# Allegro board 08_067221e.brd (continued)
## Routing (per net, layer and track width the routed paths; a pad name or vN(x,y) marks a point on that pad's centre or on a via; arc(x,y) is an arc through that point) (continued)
GND_ISO: length 25.4
  TOP w0.508: 170.42,21.67 P22.1 170.42,19.56 ; R65.1 162.36,35.94 ; R65.1 161.79,35.32 ; R65.1 161.79,36.56 ; P22.8 173.25,28.93
  L2_GND w0.508: P22.8 173.25,28.93 ; 170.67,21.41 P22.1 170.67,19.82
  L3_SIG w0.508: P22.8 173.25,28.93 ; 170.67,19.82 P22.1 170.67,21.41
  L5_GND w0.508: 170.67,19.82 P22.1 170.67,21.41 ; P22.8 173.25,28.93
  BOTTOM w0.508: 173.25,28.85 P22.8 P22.6 ; 165,32.52 R247.2 ; R247.2 165,34.79 ; R247.2 164.22,33.66 ; 170.42,19.56 P22.1 170.42,21.67
  vias: v1(150.62,33.53) v1(151.76,33.53) v1(152.78,33.53) v1(153.8,33.53) v1(154.81,33.53) v1(155.83,33.53) v1(156.84,33.53) v1(157.61,33.53) v1(157.66,31.09) v1(157.66,29.82) v1(160.28,31.35) v1(160.28,30.08) v1(161.8,34.16) v1(162.69,35.94) v1(162.81,33.15) v1(163.83,34.42) v1(163.83,33.66) v1(163.83,32.89) v1(163.83,32.13) v1(164.97,30.99) v1(165.35,26.16) v1(165.99,29.97) v1(166.81,12) v1(166.81,11.37) v1(166.81,10.73) v1(166.88,29.08) v1(167.45,12) v1(167.45,11.37) v1(167.45,10.73) v1(167.8,23.71) v1(168.1,27.12) v1(168.08,12) v1(168.08,11.37) v1(168.08,10.73) v1(168.96,23.18) v1(169,26.22) v1(170.1,22.62) v1(170.2,25.8)
GND_SHIELD_A: length 112.3
  TOP w0.508: P22.14 176.15,28.45 175.26,28.45 175.26,19.94 176.15,19.94 P22.13
  TOP w0.635: TP4.1 175.26,12.98 C99.2 176.15,13.87 P22.13
  L2_GND w0.508: P22.14 176.15,28.45 175.26,28.45 175.26,19.94 176.15,19.94 P22.13
  L3_SIG w0.508: P22.14 176.15,28.45 175.26,28.45 175.26,19.94 176.15,19.94 P22.13
  L4_PWR w0.508: P22.13 176.15,19.94 175.26,19.94 175.26,28.45 176.15,28.45 P22.14
  L5_GND w0.508: P22.14 176.15,28.45 175.26,28.45 175.26,19.94 176.15,19.94 P22.13
  BOTTOM w0.508: P22.14 176.15,28.45 175.26,28.45 175.26,19.94 176.15,19.94 P22.13
VDD_3V3: length 147.9
  TOP w0.254: U6.56 24.56,44.78 24.01,45.33 24.01,46.48 v1(24,46.48) C27.2 ; U7.45 C107.2 ; U6.38 33.71,46.62 34.04,46.95 34.25,46.95 34.67,47.37 C26.2 ; U6.18 34.21,35.81 34.46,35.56 v1(34.92,35.56) ; v1(108.2,40.64) 108.2,40.12 108.37,39.96 108.37,39.49 108.19,39.32 U9.46 ; U6.2 26.21,35.18 25.77,34.75 C56.2 ; C109.2 52.19,32.69 52.57,33.08 U7.51 ; U7.5 C110.2 ; C60.1 58.55,31.97 58.08,32.45 U7.62 ; U7.32 C66.2
  TOP w0.406: R53.2 v1(129.28,14.22) ; v1(128.37,17.39) C171.1 129.17,17.4 U27.5 ; R126.2 v1(137.29,19.94) ; v1(133.22,17.39) C170.1 133.99,17.4 U26.5 ; R39.2 v1(134.11,14.22) ; R122.2 v1(132.59,19.94)
  TOP w0.508: C66.2 51.63,47.17 v1(51.63,47.94) ; v1(47.18,37.4) 47.92,37.4 C107.2 ; C56.2 v1(25.77,34.04) ; v1(52.2,31.56) 52.2,32.25 C109.2 ; v1(146.18,18.65) C169.1 146.19,17.91 U25.5 ; R243.2 v1(129.04,10.67) ; v1(82.68,14.86) C176.2 ; U28.5 139.21,17.91 C172.2 v1(139.19,18.67) ; v1(54.23,53.85) 54.23,54.56 R33.2 ; U24.5 120.58,64.58 v1(121.67,64.58) ; v1(108.2,41.15) v1(108.2,40.64) ; DS1.A 129.23,62.74 v1(130.43,62.74) ; R187.1 63.83,44.26 v1(63.82,44.26) ; v1(34.92,35.56) 35.43,35.06 C129.2 ; E12.2 125.49,15.56 ; E12.2 124.74,16.43 ; E12.2 124.74,14.68 ; v1(115.95,10.67) R148.2 ; R12.2 v1(113.03,22.99) R22.2 ; C26.2 v1(35.19,46.74) ; R107.1 v1(38.48,38.23) ; R118.1 v1(114.93,25.4) ; R180.2 v1(156.6,18.16) ; R74.2 v1(142.88,4.06) ; v1(136.9,11.95) C4.1 E16.2 ; U15.8 125.22,12.18 C94.1 v1(125.96,12.19) ; R15.2 v1(130.55,10.67) ; v1(116.9,63.88) C1.2 U1.5 ; v1(114.87,66.04) R2.1 ; v1(115.95,9.4) R139.2 ; R26.2 v1(130.55,8.13) ; v1(60.2,29.59) 60.19,29.6 v1(60.19,30.33) 59.51,31.01 C108.2 C60.1 ; R238.2 v1(147.7,19.43) ; v1(115.95,8.13) R137.2 ; v1(98.42,15.24) C179.2 ; R19.2 v1(130.55,9.4) ; v1(62.67,38.73) 62.67,37.95 C110.2 ; v1(115.51,67.63) R101.1 ; E9.2 v1(12.7,45.94) ; R95.2 v1(145.92,14.1) ; v1(85.85,14.1) R119.1 ; v1(51.05,50.03) R142.2 ; v1(111.57,66.36) R5.1 ; v1(118.63,57.44) C163.2 C5.2 U2.4 117.71,61.69 R9.1 ; v1(37.44,27.31) C67.1 39.75,27.31 Y1.4 39.89,27.31 R115.2
  L4_PWR w0.508: 81.12,10.63 P4.3 ; P4.3 82.71,10.63 ; P4.3 81.12,12.23 ; P4.3 82.71,12.23 ; 98.39,10.63 P6.2 ; P6.2 99.98,12.23 ; P6.2 98.39,12.23 ; P6.2 99.98,10.63 ; 64.71,46.23 TP24.1 ; TP24.1 64.71,48 ; TP24.1 66.48,46.23 ; TP24.1 66.48,48 ; P8.7 47.24,50.92 ; P8.7 45.47,49.15 ; P8.7 47.24,49.15 ; P8.7 45.47,50.92 ; 7.17,56 JP47.1 7.17,54.23
  BOTTOM w0.305: v1(14.1,36.2) 14.1,36.65 13.79,36.96 11.94,36.96 11.74,36.76 C175.2 11.74,35.74 11.3,35.3 U4.5
  BOTTOM w0.381: v1(70.48,15.68) 69.66,15.68 D8.5 D8.2 ; v1(70.46,18.54) 69.66,18.54 D9.2 D9.5
  BOTTOM w0.508: v1(58.8,16.38) 60.47,16.38 U20.4 ; v1(161.66,4.08) R231.1 ; v1(111.5,57.72) R166.2 v1(112.27,56.9) ; v1(50.48,27.24) C154.2 U5.8 ; R185.2 50.21,42.48 v1(51.37,42.48) ; v1(108.2,40.64) v1(108.2,41.15) C124.2 C97.2 ; U17.8 C145.2 34.48,17.32 v1(34.48,18.1) 34.47,18.11 C82.2 ; Q3.3 22.86,48.02 R175.2 ; v1(100.15,33.02) 100.94,33.8 E1.1 ; U18.8 C146.2 22.1,17.32 v1(22.1,18.1) ; R174.2 2.98,51.82 JP47.1 ; v1(87.69,61.85) R161.2
  BOTTOM w1.016: v1(63.82,44.26) 65.6,46.03 TP24.1
  vias: v1(19.94,58.29) v1(19.94,56.77) v1(20.57,57.53) v1(21.72,49.28) v1(21.72,48.77) v1(36.7,30.1) v1(36.7,29.46) v1(54.23,53.02) v1(54.23,52.2) v1(54.99,53.85) v1(54.99,53.02) v1(54.99,52.2) v1(60.12,51.26) v1(60.13,50.48) v1(60.88,51.26) v1(60.88,50.5) v1(61.64,51.26) v1(61.64,50.5) v1(62.23,29.97) v1(62.23,29.34) v1(62.23,28.7) v1(62.87,29.97) v1(62.87,29.34) v1(62.87,28.7) v1(70.36,13.46) v1(70.36,12.57) v1(125.86,16.26) v1(125.86,15.62) v1(125.86,14.99) v1(128.27,39.12) v1(128.27,38.61) v1(128.78,39.12) v1(128.78,38.61)
VDD_5V: length 22.5
  TOP w0.508: L1.2 v1(158.75,47.79)
  L3_SIG w0.508: 92.2,51.81 TP3.1 ; TP3.1 93.98,51.81 ; TP3.1 93.98,50.04 ; TP3.1 92.2,50.04
  BOTTOM w0.508: v1(158.75,47.79) D10.C 159.51,45.71 160.02,45.2 160.02,40.89 161.26,39.65 P10.9
  vias: v1(89.47,52.07) v1(89.47,51.31) v1(90.3,52.07) v1(90.3,51.31)
VDD_5V_BPORT: length 3.1
  TOP w0.508: R36.2 86.85,53.8 v1(85.47,53.8)
  BOTTOM w0.508: v1(112.27,54.61) R165.2 v1(111.5,55.44)
  vias: v1(85.47,53.09)
1452_RESET: length 122.4
  TOP w0.178: U6.24 35.65,39.28 R107.2 36.96,37.98 36.96,37.62 v1(37.21,37.36)
  TOP w0.203: v1(126.05,64.9) R6.1
  L3_SIG w0.203: v1(126.05,64.9) 124.4,63.25 114.55,63.25 112.1,65.7 102.08,65.7 98.74,62.36 90.3,62.36 89.79,62.86 89.79,64.14 89.28,64.64 88.01,64.64 87.5,64.14 85.85,64.14 85.5,64.48 82.2,64.48 78.44,60.72 78.44,48.53 72.81,42.9 66,42.9 65.98,42.93 65.97,42.93 64,44.89 59.5,44.89 v1(58.55,43.94)
  BOTTOM w0.178: v1(58.55,43.94) 58.55,42.93 57.28,41.66 49.78,41.66 48.51,40.39 41.91,40.39 41.02,41.27 39.62,41.27 39.12,40.77 39.12,37.72 38.76,37.36 v1(37.21,37.36) 36.89,37.36 36.71,37.54 R107.2
AD243X_ADR1_SS: length 142.6
  TOP w0.178: R195.1 v1(112.27,25.4) ; P15.23 17.2,42.67 15.11,42.67 14.68,42.24 14.68,35.74 14,35.05 R100.1
  L3_SIG w0.178: v1(112.27,25.4) 111.37,24.49 105.04,24.49 104.26,25.27 96.01,25.27 93.73,27.56 67.18,27.56 66.42,26.8 57.95,26.8 56.11,28.63 56.11,32.66 55.3,33.48 51.64,33.48 51.04,32.88 49.17,32.88 47.53,31.24 20.7,31.24 19.48,32.46 19.48,34.37 18.92,34.92 17.58,34.92 17.14,35.36 17.14,36.7 17.54,37.1 17.54,37.83 17.22,38.15 17.22,42.7 P15.23
  BOTTOM w0.203: P32.79 12,44.13 14.48,46.61 14.48,47.12 14.86,47.5 16.76,47.5 17.14,47.12 17.14,45.01 P15.23
AD243X_AN: length 22.9
  TOP w0.241: U9.28 114.09,33.93 arc(114.14,33.96) 114.2,33.97 115.57,33.97 arc(115.69,33.95) 115.78,33.88 120.11,29.56 122.51,27.15 arc(123.23,26.67) 124.08,26.5 129.04,26.5 C30.2 129.46,26.21 129.76,26.5 130.34,26.5 130.76,26.08 L2.2 130.98,26.08 131.41,26.51 132.31,26.51 L4.1
AD243X_AP: length 22.9
  TOP w0.241: L5.1 132.31,26.92 131.45,26.92 131.04,27.33 L3.1 130.71,27.33 130.29,26.91 129.81,26.91 129.51,27.21 C30.1 129.04,26.91 124.08,26.91 arc(123.39,27.05) 122.8,27.44 120.4,29.84 116.07,34.17 arc(115.84,34.32) 115.57,34.38 114.2,34.38 arc(114.14,34.39) 114.09,34.42 U9.29
AD243X_BCLK: length 185.1
  TOP w0.178: C10.2 v1(35.69,51) R45.2 ; R62.2 v1(21.46,45.34) ; R241.1 v1(99.06,32.38) 98.55,32.38 98.17,32 98.17,30.39 98.72,29.84 102.14,29.84 103.33,28.65 103.33,23.54 106.81,20.07 JP1.4
  L3_SIG w0.203: v1(56.4,51.05) 56.02,50.67 54.42,50.67 53.15,51.94 53.15,53.59 51.66,55.08 50.29,55.08 48.01,57.37 44.59,57.37 44.33,57.62 39.71,57.62 37.59,55.5 37.59,50.93 37.13,50.46 36.22,50.46 v1(35.69,51)
  BOTTOM w0.178: v1(99.06,32.38) 98.54,32.91 98.54,34.44 99.06,34.96 99.06,35.81 99.07,35.82 99.07,36.57 94.2,41.44 64.29,41.44 58.93,46.8 58.93,50.35 57.7,51.57 56.93,51.57 v1(56.4,51.05) R172.2 ; C151.1 10.55,17.52 10.92,17.14 17.07,17.14 P15.1 19.47,17.01 19.47,18.71 21.34,20.57 21.34,29 22.86,30.52 22.86,34.42 23.37,34.92 23.37,41.22 21.48,43.11 21.48,44.41 21.46,44.42 v1(21.46,45.34) 21.07,45.73 21.07,54.34 21.72,54.99 29.69,54.99 31.51,53.17 31.51,51.3 32.74,50.06 35.22,50.06 35.69,50.53 v1(35.69,51)
  BOTTOM w0.203: C151.1 10.42,18.8 10.42,18.83 9.91,19.34 9.91,19.8 9.71,20 P32.3
AD243X_BCM: length 8.9
  TOP w0.254: v1(112.46,37.02) 112.86,37.42 U9.35
  BOTTOM w0.381: v1(112.46,37.02) 112.46,37.34 112.08,37.72 111.93,37.72 C13.2 111.42,38.23 111.42,41.57 112.65,42.8 C14.2
AD243X_BN: length 23
  TOP w0.241: L11.1 132.32,44.33 131.62,44.33 131.19,44.77 L9.1 130.66,44.77 130.23,44.34 129.72,44.34 129.42,44.63 C45.1 129.04,44.34 124.08,44.34 arc(123.27,44.17) 122.58,43.72 120.97,42.1 115.87,37 arc(115.73,36.91) 115.57,36.88 114.4,36.88 114.36,36.92 U9.34
AD243X_BP: length 22.9
  TOP w0.241: U9.33 114.36,36.42 114.4,36.47 115.57,36.47 arc(115.89,36.53) 116.16,36.71 121.26,41.81 122.87,43.43 arc(123.43,43.8) 124.08,43.93 129.04,43.93 C45.2 129.4,43.63 129.7,43.93 130.25,43.93 130.68,43.5 L8.2 131.17,43.5 131.6,43.93 132.32,43.93 L10.1
AD243X_DRX0: length 145.7
  TOP w0.178: R47.2 v1(34.54,51) C11.2
  TOP w0.203: JP6.1 88.42,38.86 68.83,38.86 66.92,40.77 v1(66.92,43.94) ; R57.2 53,51.13 v1(50.46,51.13)
  L3_SIG w0.203: v1(66.92,43.94) 66.29,43.94 63.78,46.46 63.78,47.79 61.96,49.61 59.77,49.61 59.23,50.15 51.71,50.15 51.29,50.56 51.03,50.56 v1(50.46,51.13) 50.8,51.47 50.8,52.91 50.55,53.16 50.55,53.98 47.56,56.96 43.62,56.96 43.37,57.21 40.07,57.21 38.86,56.01 38.86,51.62 37.3,50.06 35.48,50.06 v1(34.54,51)
  BOTTOM w0.178: v1(34.54,51) 33.98,51.56 33.4,51.56 32.99,51.97 32.99,54.73 31.85,55.88 21.34,55.88 20.31,54.85 20.31,43.2 22.61,40.9 22.61,35.43 21.08,33.91 21.08,29.9 20.32,29.13 20.32,25.47 P15.7 17.21,22.36 15.33,22.36 15.15,22.54 P32.11
AD243X_DRX1: length 147.5
  TOP w0.178: R48.2 C12.2 32.65,51.7 32.77,51.82 32.77,52.58 v1(33.53,53.34)
  TOP w0.203: JP9.1 88.37,42.29 71.95,42.29 v1(70.29,43.94)
  L3_SIG w0.203: v1(70.29,43.94) 69.66,43.31 66.17,43.31 63.37,46.1 63.37,47.62 61.86,49.14 59.42,49.14 59.28,49.28 58.8,49.28 58.34,49.74 51.52,49.74 51.27,49.5 50.83,49.5 49.82,50.51 49.82,51.33 50.34,51.86 50.34,52.79 48.66,54.47 48.02,54.47 45.97,56.52 43.43,56.52 43.14,56.81 40.3,56.81 39.36,55.87 39.36,51.54 37.47,49.65 33.41,49.65 32.51,50.55 32.51,52.32 v1(33.53,53.34)
  BOTTOM w0.178: v1(33.53,53.34) 33.53,54.74 32,56.26 21.18,56.26 21.17,56.25 21.07,56.25 19.93,55.11 19.93,43.04 22.2,40.77 22.2,35.66 20.7,34.16 20.7,30.09 19.81,29.2 19.81,27.51 P15.9 17.13,24.83 14.67,24.83 13.65,23.81 P32.15
AD243X_GPIO7: length 145.9
  TOP w0.178: JP1.2 113.59,21.29 107.11,21.29 106.3,22.1 R14.1
  L3_SIG w0.203: v1(12.37,29.97) 12.37,26.23 13.72,24.89 18.8,24.89 19.67,24.02 19.67,22.19 20.07,21.79 20.07,20.19 20.96,19.3 30.1,19.3 30.73,19.94 34.75,19.94 36.3,18.39 47.02,18.39 48.01,17.4 67.44,17.4 67.56,17.27 69.66,17.27 70.16,17.78 70.8,17.78 72.06,19.04 96.33,19.04 98.61,16.75 105.55,16.75 110.07,12.23 115.14,12.23 116.94,14.03 116.94,15.78 114.81,17.91 JP1.2
  BOTTOM w0.178: R189.1 11.97,30.86 11.34,31.5 11.34,32.93 11.55,33.14 11.83,33.14 12.06,33.38 12.06,34.16 12.19,34.29 U4.2
  BOTTOM w0.203: v1(12.37,29.97) 12.37,30.78 R189.1
AD243X_IOVDD: length 14.9
  TOP w0.178: v1(110.87,30.73) 111.19,31.06 U9.21
  TOP w0.203: v1(107.42,32.68) 107.18,32.93 U9.11
  L4_PWR w0.508: 67.82,24.77 TP10.1 ; TP10.1 69.59,26.54 ; TP10.1 69.59,24.77 ; TP10.1 67.82,26.54
  BOTTOM w0.508: R7.2 110.87,29.97 v1(110.87,30.73) 110.87,31.49 C22.2 ; E1.2 105.16,34.8 106.55,33.41 C40.2 107.42,33.36 v1(107.42,32.68)
AD243X_IRQ: length 167.1
  TOP w0.178: R69.1 30.61,50.93 30.35,51.18 30.35,52.32 v1(30.99,52.96) ; R38.2 101.97,27.91 101.57,28.32 v1(100.33,28.32) ; U9.24 112.69,29.55 113.92,28.32 114.65,28.32 114.93,28.03 R118.2 115.45,27.42 115.82,27.05 v1(115.82,25.4) ; P15.29 19.68,50.09 19.68,43.27 18.96,42.54 17.78,42.54 17.02,41.78 v1(17.02,37.46)
  L3_SIG w0.178: P15.29 18.29,51.43 17.22,52.5 17.22,54.82 17.51,55.11 29.6,55.11 30.99,53.72 v1(30.99,52.96) 30.35,52.32 30.35,51.05 32.53,48.88 37.86,48.88 39.15,50.16 v1(39.5,50.16)
  BOTTOM w0.178: v1(39.5,50.16) 40.64,51.31 47.62,51.31 48.13,50.8 48.13,48.51 54.23,42.42 56.9,42.42 57.66,43.18 57.66,44.32 58.17,44.83 58.93,44.83 63.75,40 66.99,40 68.55,38.45 95.57,38.45 97.27,36.76 97.27,31.3 98.6,29.97 98.68,29.97 v1(100.33,28.32) 103.63,25.02 104.51,25.02 105.15,24.38 111.99,24.38 113.53,25.92 115.3,25.92 v1(115.82,25.4) ; v1(17.02,37.46) 14.99,37.46 13.89,38.56 10.87,38.56 10.1,37.78 P32.59
AD243X_ISENSEP: length 29.6
  TOP w0.203: U9.42 110.19,39.15 110.29,39.25 110.29,39.56 110.81,40.08 110.81,42.81 112.79,44.79 112.79,47.41 111.54,48.65 102.73,48.65 v1(97.28,54.1)
  BOTTOM w0.305: R182.1 96.77,53.59 v1(97.28,54.1)
AD243X_MISO: length 180.1
  TOP w0.178: R86.1 v1(2.42,39.05)
  L3_SIG w0.178: v1(152.65,9.14) 151.94,8.43 136.09,8.43 133.05,5.38 114.71,5.38 106.13,13.96 86.45,13.96 85.95,13.46 71.98,13.46 70.57,12.05 70.14,12.05 68.48,13.72 58.36,13.72 57.22,14.86 47.34,14.86 45.52,16.68 22.05,16.68 19,13.63 13.39,13.63 12.36,14.66 12.36,17.58 5.33,24.61 5.33,36.14 v1(2.42,39.05)
  BOTTOM w0.203: R232.1 v1(152.65,9.14)
AD243X_MISO_SW: length 128.4
  TOP w0.178: v1(6.86,35.19) 6.86,35.55 6.68,35.72 2.62,35.72 2.42,35.93 R92.1 ; R120.1 v1(108.84,25.4)
  L3_SIG w0.178: P15.19 19.46,37.62 19.46,35.66 20.24,34.87 20.24,33.1 21.34,32 47.21,32 48.85,33.64 50.73,33.64 51.32,34.24 55.86,34.24 56.88,33.22 56.88,28.94 58.26,27.56 66.11,27.56 66.87,28.32 94.23,28.32 96.39,26.17 108.06,26.17 v1(108.84,25.4) ; v1(6.86,35.19) 7.89,35.19 8.13,35.43 8.13,38.86 7.94,39.05 v1(6.86,39.05)
  BOTTOM w0.178: P15.19 17.07,40 12.95,40 12,39.05 P32.63 v1(6.86,39.05)
AD243X_MOSI: length 179.6
  TOP w0.178: R97.1 v1(2.42,34.1)
  L3_SIG w0.178: v1(156.45,9.13) 155.32,8 136.21,8 133.2,5 114.55,5 105.98,13.58 87.15,13.58 86.38,12.81 71.87,12.81 70.73,11.67 69.98,11.67 68.32,13.33 58.2,13.33 57.06,14.48 47.12,14.48 45.34,16.26 22.23,16.26 19.18,13.21 13.21,13.21 11.94,14.48 11.94,17.4 4.95,24.38 4.95,31.57 v1(2.42,34.1)
  BOTTOM w0.203: R223.1 v1(156.45,9.13)
AD243X_MOSI_SW: length 139.1
  TOP w0.178: v1(6.86,30.21) 2.93,30.21 2.42,30.73 R111.1 ; R11.1 v1(109.98,25.4)
  L3_SIG w0.178: P15.21 18.34,40.4 19.84,38.9 19.84,35.88 20.7,35.02 20.7,33.27 21.59,32.38 47.06,32.38 48.69,34.02 50.57,34.02 51.16,34.62 56.02,34.62 57.26,33.38 57.26,29.1 58.42,27.94 65.95,27.94 66.71,28.7 94.49,28.7 96.64,26.55 108.83,26.55 v1(109.98,25.4) ; v1(6.86,40.32) 8.19,40.32 8.51,40 8.51,30.48 8.24,30.21 v1(6.86,30.21)
  BOTTOM w0.178: P15.21 17.07,42.54 14.1,42.54 11.87,40.32 P32.67 v1(6.86,40.32)
AD243X_RESET: length 106.1
  TOP w0.203: v1(112.39,32.64) 112.72,32.64 112.93,32.42 U9.25 ; R3.1 125.34,65.91 v1(126.05,65.91) 127.57,65.91 P23.1
  L3_SIG w0.203: v1(126.05,65.91) 126.64,65.32 126.64,63.6 125.28,62.23 113.79,62.23 112.01,64.01 102.36,64.01 99.31,60.96 93.57,60.96 90.3,57.68 85.37,57.68 80.01,52.32 80.01,48.98 85.91,43.08 94.8,43.08 99.5,38.38 100.48,38.38 104.31,34.54 105.34,34.54 106.61,33.27 107.7,33.27 108.33,32.64 v1(112.39,32.64)
  BOTTOM w0.203: v1(112.39,32.64) C173.2 111.69,29.67 110.98,28.96 R7.1
AD243X_SCK: length 178.4
  TOP w0.178: R106.1 13.45,33.68 12.79,33.02 11.81,33.02 11.68,33.15 9.52,33.15 9.14,32.77 9.14,30.48 9.65,29.97 v1(10.29,29.97)
  L3_SIG w0.178: v1(155.19,9.14) 154.56,9.78 152.27,9.78 151.3,8.81 135.94,8.81 132.89,5.76 114.87,5.76 106.29,14.34 86.5,14.34 86.11,14.73 83.85,14.73 82.96,13.84 79.6,13.84 79.34,14.1 58.52,14.1 57.37,15.24 47.5,15.24 45.67,17.06 21.89,17.06 18.84,14.02 13.54,14.02 12.75,14.81 12.75,17.73 8.76,21.72 8.76,28.45 v1(10.29,29.97)
  BOTTOM w0.203: R235.1 v1(155.19,9.14)
AD243X_SCK_SW: length 136.5
  TOP w0.178: R113.1 14.05,30.86 14.22,31.04 14.22,31.5 15.11,32.38 18.92,32.38 19.56,33.02 19.56,34.98 P15.17 ; R199.1 v1(111.12,25.4)
  L3_SIG w0.178: P15.17 19.86,34.67 19.86,32.84 21.08,31.62 47.37,31.62 49.01,33.26 50.88,33.26 51.48,33.86 55.55,33.86 56.5,32.91 56.5,28.79 58.1,27.18 66.26,27.18 67.03,27.94 93.98,27.94 96.27,25.65 104.41,25.65 105.19,24.87 110.2,24.87 110.72,25.4 v1(111.12,25.4)
  BOTTOM w0.178: P32.71 10.35,41.59 10.54,41.4 12.06,41.4 14.22,43.56 14.22,44.32 14.99,45.09 16.26,45.09 17.02,44.32 17.02,43.31 17.78,42.54 18.8,42.54 19.46,41.88 19.46,37.31 P15.17
AD243X_SCL: length 187.9
  TOP w0.178: v1(130.05,18.8) R70.2 R122.1 ; P15.25 18.34,46.43 17.14,47.62 11.3,47.62 v1(10.67,48.26) ; R35.2 v1(129.03,8.13)
  TOP w0.203: U9.16 108.69,29.45 107.96,28.71 107.96,22.62 v1(107.31,21.97)
  L3_SIG w0.178: v1(107.31,21.97) 107.77,21.97 107.95,21.79 107.95,19.94 106.17,18.16 99.57,18.16 97.15,20.57 70.61,20.57 69.46,19.42 60.75,19.42 60.47,19.7 58.4,19.7 57.74,19.04 52.37,19.04 50.58,20.83 46.45,20.83 45.45,19.82 36.94,19.82 35.56,21.21 23.17,21.21 22.79,20.83 22.13,20.83 20.57,22.38 20.57,27.92 18.8,29.69 15.64,29.69 12.83,32.51 12.83,43.21 12.22,43.81 10.29,43.81 9.52,44.58 9.52,48.34 9.7,48.51 10.41,48.51 v1(10.67,48.26)
  BOTTOM w0.178: v1(107.31,21.97) 108.2,21.97 108.33,22.09 118.74,22.09 120.18,23.53 124.04,23.53 126.75,20.83 128.02,20.83 v1(130.05,18.8) 130.05,11.97 129.56,11.48 129.56,8.65 v1(129.03,8.13)
AD243X_SDA: length 199.6
  TOP w0.178: R203.2 v1(129.03,6.86) ; P15.27 18.34,48.97 17.27,50.04 11.43,50.04 v1(10.67,49.28) ; U9.15 108.19,29.58 107.57,28.96 107.57,23.11 v1(107.31,22.86) ; v1(134.74,18.8) R55.2 R126.1
  L3_SIG w0.178: v1(10.67,49.28) 10.41,49.02 9.52,49.02 9.02,48.51 9.02,44.45 10.03,43.43 12.06,43.43 12.45,43.05 12.45,32.26 14.1,30.61 14.1,27.69 14.63,27.15 19.71,27.15 20.07,26.8 20.07,22.35 21.97,20.45 22.95,20.45 23.33,20.83 35.4,20.83 36.79,19.44 45.61,19.44 46.61,20.45 50.42,20.45 52.21,18.66 57.9,18.66 58.56,19.32 60.31,19.32 60.59,19.04 69.61,19.04 70.77,20.19 97,20.19 99.41,17.78 106.33,17.78 108.33,19.78 108.33,21.95 107.93,22.35 107.82,22.35 v1(107.31,22.86)
  BOTTOM w0.178: v1(107.31,22.86) 108.2,22.86 108.59,22.47 118.58,22.47 120.02,23.91 124.2,23.91 126.9,21.21 128.52,21.21 131.57,18.16 132.72,18.16 133.35,18.8 v1(134.74,18.8) 134.74,16.12 129.94,11.32 129.94,7.76 v1(129.03,6.86)
AD243X_SIO2: length 160.2
  TOP w0.178: v1(22.23,21.59) 20.96,21.59 20.45,22.1 20.45,28.07 19.94,28.58 P15.11 ; v1(101.98,24.13) 101.97,24.14 R34.2 101.97,25.83 102.84,26.7 102.84,28.6 102.02,29.43 98.08,29.43 97.66,29.84 97.66,34.42 98.17,34.92 R98.1 ; R81.1 R68.1 v1(21.59,38.99) ; R84.2 v1(28.07,51.01)
  L3_SIG w0.178: v1(101.98,24.13) 100.33,24.13 97.55,21.35 57.42,21.35 56.26,20.19 52.7,20.19 51.07,21.83 22.47,21.83 v1(22.23,21.59) ; v1(21.59,38.99) 22.35,39.75 22.35,45.47 21.86,45.96 21.22,45.96 20.83,46.35 20.83,46.99 19.81,48.01 19.81,51.56 20.18,51.93 23.58,51.93 24.09,52.43 26.64,52.43 v1(28.07,51.01)
  BOTTOM w0.178: P32.19 10.49,25.08 C141.1 10.55,25.66 10.79,25.91 11.94,25.91 13.27,27.24 17.02,27.24 18.34,28.56 P15.11 20.32,30.55 20.32,34.54 20.96,35.18 20.96,38.35 v1(21.59,38.99)
AD243X_SIO3: length 129.2
  TOP w0.178: v1(103.85,24.48) 103.85,28.86 102.49,30.23 101.14,30.23 100.85,30.52 R114.1 C64.1 ; v1(20.51,40.32) 20.51,41.08 21.34,41.91 R67.1
  L3_SIG w0.203: v1(22.23,22.48) 22.48,22.23 51.23,22.23 51.98,21.48 54.45,21.48 54.84,21.87 71.27,21.87 72.13,22.73 98.38,22.73 100.41,24.77 103.56,24.77 v1(103.85,24.48)
  L4_PWR w0.178: v1(22.23,22.48) 21.34,22.48 20.96,22.86 20.96,29.59 19.43,31.12 P15.13
  BOTTOM w0.178: P32.23 11.82,26.35 15.22,29.76 16.98,29.76 P15.13 19.94,32.71 19.94,34.8 20.51,35.37 v1(20.51,40.32)
AD243X_SIO4: length 152.2
  TOP w0.178: v1(18.29,55.75) 19.43,55.75 20.19,54.99 20.19,43.05 ; 20.19,43.05 19.59,42.45 19.59,38.01 19.05,37.46 17.78,37.46 17.02,36.7 17.02,34.98 P15.15 ; 20.19,43.05 R66.1 ; C71.2 v1(105.16,25.65) R121.1
  L3_SIG w0.178: v1(57.48,51.05) 57.84,51.41 57.84,52.7 56.06,54.48 53.85,54.48 52.45,55.88 50.83,55.88 49.64,57.06 49.64,57.07 48.55,58.17 44.92,58.17 44.53,58.56 39,58.56 36.2,55.75 v1(18.29,55.75)
  BOTTOM w0.178: v1(57.48,51.05) R171.2 58.19,50.35 58.55,49.99 58.55,46.61 64.12,41.03 67.04,41.03 68.86,39.21 95.89,39.21 98.69,36.41 98.69,35.98 98.68,35.97 98.68,35.11 98.16,34.59 98.16,32.52 105.03,25.65 v1(105.16,25.65) ; P15.15 17.07,32.38 15.24,32.38 14.61,31.75 14.61,29.71 11.82,26.92 10.41,26.92 9.72,27.62 P32.27
AD243X_SWP: length 19.4
  TOP w0.203: U9.41 110.69,39.39 111.35,40.05 111.35,42.77 113.03,44.45 113.03,44.46 113.2,44.63 113.2,47.58 111.71,49.06 107.68,49.06 v1(107.38,49.36)
  BOTTOM w0.203: C174.2 v1(107.38,49.36)
  BOTTOM w0.508: Q4.4 106.34,49.28 C174.2
AD243X_SYNC: length 162.2
  TOP w0.178: v1(99.06,33.66) R240.1 ; R63.2 v1(20.96,44.2) ; R44.2 v1(36.83,51) C9.2
  L3_SIG w0.203: v1(36.83,51) 36.3,51.53 36.3,55.09 39.37,58.17 44.36,58.17 44.76,57.77 48.38,57.77 50.66,55.49 51.83,55.49 53.56,53.76 53.56,52.12 54.31,51.36 v1(55.37,51.36)
  BOTTOM w0.178: v1(36.83,51) 36.25,51.57 35.42,51.57 35.13,51.28 35.13,50.69 34.91,50.47 32.97,50.47 32.61,50.83 32.61,54.25 31.5,55.37 21.46,55.37 20.69,54.6 20.69,44.46 v1(20.96,44.2) 20.96,43.09 22.99,41.06 22.99,35.18 22.36,34.56 22.36,30.6 20.83,29.07 20.83,20.9 P15.3 17.07,19.69 14.73,19.69 14.48,19.43 10.75,19.43 10.55,19.63 C152.1 ; v1(99.06,33.66) 99.06,34.42 99.44,34.8 99.44,35.65 99.45,35.66 99.45,36.73 94.33,41.85 64.46,41.85 59.33,46.97 59.33,50.48 57.86,51.96 55.97,51.96 v1(55.37,51.36) 55.33,51.31 R173.2
  BOTTOM w0.203: C152.1 10.55,20.1 10.04,20.61 10.04,21.07 9.84,21.27 P32.7
AD243X_VBUS: length 51.3
  TOP w0.178: C46.2 110.71,43.27 112.39,44.96 112.39,47.24 111.38,48.26 102.23,48.26 v1(96.39,54.1) ; U9.43 109.69,39.21 109.89,39.41 109.89,39.72 110.21,40.04 110.21,40.47
  TOP w0.508: TP13.1 108.46,46.29 108.46,43.78 108.97,43.27 C46.2 110.21,43.04 110.21,40.47 ; TP25.1 66.55,50.92 ; TP25.1 64.77,50.92 ; TP25.1 66.55,49.15 ; TP25.1 64.77,49.15
  L4_PWR w0.508: 108.1,47.12 TP13.1 109.28,48.3
  BOTTOM w0.305: 81.18,62.8 U19.8 ; v1(96.39,54.1) 96.77,54.48 R182.2
  BOTTOM w0.508: R154.1 v1(88.46,64.01) ; 54.62,60.94 R162.2 ; R162.2 55.37,60.29 ; R162.2 56.12,60.94 ; v1(82.17,66.61) 82.17,64.96 C101.2 81.18,63.84 81.18,62.8
  vias: v1(2.86,29.08) v1(2.86,28.19) v1(2.86,27.37) v1(2.86,26.48) v1(3.81,29.08) v1(3.81,28.19) v1(3.81,27.37) v1(3.81,26.48) v1(57.98,58.04) v1(58.61,58.04) v1(95.88,58.29) v1(95.88,57.61) v1(95.88,56.9) v1(96.65,58.29) v1(96.65,57.66) v1(96.65,56.9) v1(97.41,58.29) v1(97.41,57.66) v1(97.41,56.9)
AD243X_VOUT1: length 122.8
  TOP w0.254: v1(107.81,39.73) 107.42,39.73 107.19,39.5 107.19,39.24 ; U9.2 105.5,37.42 105.35,37.27 v1(105.35,36.92) U9.3 ; 107.19,39.24 107.57,39.24 107.69,39.12 U9.47 ; 107.19,39.24 U9.48
  L3_SIG w0.508: v1(9.78,54.1) 9.78,56.65 12.24,59.11 26.04,59.11 27.3,60.36 35.99,60.36 37.07,61.44 40.23,61.44 43.94,65.15 48.36,65.15 52.55,60.96 56.39,60.96 57.21,61.79 59.37,61.79 60.33,60.83 60.33,58.93 60.83,58.42 65.78,58.42 71.75,52.45 v1(71.75,44.32)
  L4_PWR w0.508: TP11.1 98.04,45.21 ; TP11.1 96.27,43.44 ; TP11.1 96.27,45.21 ; TP11.1 98.04,43.44
  BOTTOM w0.508: v1(107.81,39.73) 107.81,38.72 107.45,38.36 C126.2 ; v1(9.78,54.1) R169.2 ; v1(71.75,44.32) TP11.1 ; v1(105.35,36.92) 105.4,36.87 C128.2
  vias: v1(99.57,39.24) v1(100.2,39.24) v1(100.84,39.24)
AD243X_VSENSEP: length 16.2
  TOP w0.203: U9.40 111.19,39.25 111.76,39.82 111.76,42.61 113.54,44.38 113.54,44.39 113.6,44.46 113.6,47.74 111.68,49.66 v1(109.22,49.66)
  BOTTOM w0.203: R181.1 v1(109.22,49.66)
AD1937_ADR0: length 4.9
  TOP w0.203: R143.2 51.05,49.03 R142.1 52.07,48.28 52.26,48.1 52.26,46.61 52.57,46.29 U7.30
AD1937_ADR1: length 3.6
  TOP w0.254: U7.35 49.64,42.42 v1(48.2,42.42)
  BOTTOM w0.203: R190.2 R185.1 49.15,42.42 v1(48.2,42.42)
AD1937_ASDATA1: length 56.6
  TOP w0.178: R71.1 v1(21.59,36.7)
  TOP w0.203: TP8.1 49.21,51.12 49.73,50.6 50.68,50.6 50.74,50.65 52.57,50.65 53.28,49.95 53.28,49.39 53.63,49.03 R57.1 R105.2 54.79,48.06 54.99,47.86 v1(54.99,46.99)
  L3_SIG w0.178: v1(21.59,36.7) 22.48,35.81 33.78,35.81 34.67,36.7 34.67,42.8 36.96,45.09 38.86,45.09 40.08,46.3 47.04,46.3 49.92,43.42 53.96,43.42 v1(54.48,43.94)
  BOTTOM w0.203: v1(54.48,43.94) 54.99,44.45 v1(54.99,46.99)
AD1937_BCLK: length 60.9
  TOP w0.178: R51.2 v1(25.78,51) C17.2 ; R58.1 56.53,48.07 v1(56.53,48.7) ; R87.1 v1(21.59,37.85)
  L3_SIG w0.178: v1(21.59,37.85) 22.48,37.85 23.24,38.61 23.24,48.51 21.72,50.04 21.72,50.75 21.89,50.93 23.66,50.93 24.25,51.52 25.32,51.52 25.78,51.05 v1(25.78,51)
  L3_SIG w0.203: v1(56.53,48.7) 55.69,48.7 53.85,46.86 50.29,46.86 47.49,49.67 47.49,50.51 46.68,51.31 42.67,51.31 41.66,50.29 41.66,49.39 39.01,46.74 37.08,46.74 36.48,47.34 29.44,47.34 v1(25.78,51)
  BOTTOM w0.178: v1(56.53,48.7) 56.53,49.22 R172.1
AD1937_CM: length 13.6
  TOP w0.254: U7.52 53.08,32.72 52.81,32.46 52.81,31.36 C112.2
  BOTTOM w0.508: v1(33.02,13.08) 33.44,13.51 C138.2 U17.5 ; v1(25.4,12.7) 25.4,13 24.89,13.51 U18.5 ; U18.3 30.06,14.78 30.18,14.65 C137.2 v1(31.12,15.37) ; U17.3 41.53,14.8 v1(43.24,14.8)
  vias: v1(53.42,27.93) v1(53.42,27.17) v1(54.18,27.93) v1(54.18,27.17) v1(54.93,27.94) v1(54.94,27.17)
AD1937_DSDATA1: length 48.9
  TOP w0.178: C18.2 v1(24.64,51) R52.2
  TOP w0.203: R104.1 57.61,48.1 v1(57.61,48.7) 55.49,50.83 54.85,50.83 53.35,52.32 TP7.1
  L3_SIG w0.203: v1(57.61,48.7) 55.07,46.16 50.1,46.16 47.62,48.64 41.7,48.64 38.86,45.8 36.95,45.8 36.36,45.21 34.8,45.21 33.68,46.33 29.31,46.33 v1(24.64,51)
  BOTTOM w0.178: v1(57.61,48.7) 57.61,49.22 R171.1
AD1937_MCLKI: length 2.8
  TOP w0.178: U7.2 62.66,36.43 R94.1 R91.1
AD1937_RESET: length 88.4
  TOP w0.203: U7.14 62.82,42.43 C162.2 R187.2 v1(62.83,44.26) ; v1(126.11,63.82) R134.1
  L3_SIG w0.203: v1(126.11,63.82) 125.03,62.74 114.17,62.74 111.62,65.29 102.25,65.29 98.82,61.86 89.78,61.86 88.01,63.63 85.47,63.63 85.09,64.01 82.3,64.01 78.84,60.55 78.84,48.36 72.97,42.49 65.83,42.49 64.63,43.69 63.4,43.69 v1(62.83,44.26)
AD1937_SYNC: length 71.1
  TOP w0.178: R50.2 v1(26.92,51) C16.2 ; R59.1 53.02,48.76 v1(53.09,48.82)
  L3_SIG w0.178: v1(27.44,36.95) 27.06,37.33 21.37,37.33 21.07,37.63 21.07,38.21 21.32,38.47 22.21,38.47 22.73,38.99 22.73,46.99 21.72,48.01 20.7,48.01 20.32,48.39 20.32,50.96 20.8,51.43 23.63,51.43 24.09,51.9 26.02,51.9 v1(26.92,51)
  L3_SIG w0.203: v1(26.92,51) 29.9,48.02 39.64,48.02 41.02,49.4 41.02,51.56 43.43,53.98 46.56,53.98 47.49,53.05 47.49,51.73 50.51,48.71 51.6,48.71 51.72,48.82 v1(53.09,48.82)
  BOTTOM w0.178: R173.1 53.73,49.35 53.21,48.82 v1(53.09,48.82) ; R183.1 27.31,36.33 27.44,36.46 v1(27.44,36.95)
ADAU1452_AUXADC0: length 27.8
  TOP w0.178: v1(29.08,36.96) 29.08,36.61 29.15,36.53 29.15,36.14 U6.8
  BOTTOM w0.203: P8.1 45.22,41.29 42.89,41.29 42.42,41.76 42.42,43.18 41.53,44.07 39.75,44.07 39.09,43.41 38.21,43.41 37.78,42.98 37.78,40.58 37.76,40.56 37.76,40.42 35.18,37.85 35.18,36.58 34.74,36.14 33.6,36.14 32.67,35.21 30,35.21 29.08,36.13 29.08,36.4 29.08,36.4 v1(29.08,36.96)
ADAU1452_AUXADC1: length 25.5
  TOP w0.178: U6.9 29.71,36.69 29.66,36.73 29.66,37.52 29.46,37.72 v1(29.08,37.72)
  BOTTOM w0.203: v1(29.08,37.72) 29.67,37.13 29.67,36.11 30.17,35.61 32.38,35.61 33.32,36.55 34.47,36.55 34.67,36.75 34.67,37.92 37.35,40.6 37.35,40.72 37.38,40.75 37.38,43.98 37.87,44.48 41.7,44.48 41.72,44.45 41.78,44.45 43.81,42.42
ADAU1452_AUXADC2: length 24.7
  TOP w0.178: U6.10 v1(30.21,36.96)
  BOTTOM w0.203: v1(30.21,36.96) 30.21,36.34 30.53,36.02 32.14,36.02 32.89,36.77 32.89,37.34 33.17,37.62 33.68,37.62 36.97,40.91 36.97,44.34 37.57,44.93 42.24,44.93 43.35,43.83 45.22,43.83 P8.3
ADAU1452_AUXADC3: length 23.6
  TOP w0.178: U6.11 30.71,36.67 30.75,36.72 30.75,37.54 30.57,37.72 v1(30.21,37.72)
  BOTTOM w0.203: v1(30.21,37.72) 30.8,37.13 30.8,36.74 31.11,36.43 31.97,36.43 32.49,36.94 32.49,37.51 33.08,38.1 33.59,38.1 36.56,41.07 36.56,44.62 37.94,46 39.12,46 39.47,46.35 41.82,46.35 42.42,45.76 43.02,45.76 43.81,44.96
ADAU1452_AUXADC4: length 23
  TOP w0.178: U6.12 31.21,36.54 31.33,36.67 v1(31.33,36.96)
  BOTTOM w0.203: P8.5 45.09,46.23 42.93,46.23 42.29,46.86 39.19,46.86 38.73,46.41 37.77,46.41 36.16,44.79 36.16,41.24 33.42,38.51 32.73,38.51 31.87,37.64 31.87,37.49 v1(31.33,36.96)
ADAU1452_AUXADC5: length 20.9
  TOP w0.178: v1(31.33,37.72) 31.7,37.72 31.88,37.54 31.88,36.73 31.71,36.56 U6.13
  BOTTOM w0.203: 43.81,47.5 38.98,47.5 38.44,46.96 37.56,46.96 35.75,45.15 35.75,41.41 33.33,38.99 32.6,38.99 v1(31.33,37.72)
ADAU1452_CLKOUT: length 35.2
  TOP w0.178: v1(63.7,37.14) R94.2 ; R88.2 v1(38.49,36.58) 38.49,36.58 39.12,37.21 39.12,40.59 39.08,40.63 39.08,41.36 TP18.1
  L3_SIG w0.178: v1(38.49,36.58) 38.49,36.57 39.12,35.94 62.5,35.94 v1(63.7,37.14)
  BOTTOM w0.178: R88.2 v1(38.49,36.58)
ADAU1452_MP6: length 157.7
  TOP w0.178: v1(30.99,52.2) 31.27,51.92 31.27,48.67 30.21,47.6 U6.45 ; R95.1 v1(148.47,14.1)
  TOP w0.203: U25.1 147.69,15.56 R95.1
  L3_SIG w0.178: v1(148.47,14.1) 148.47,20.54 145.89,23.11 127.82,23.11 126.55,24.38 119.98,24.38 116.81,27.56 113.69,27.56 112.21,29.04 109.21,29.04 106.25,32 104.24,32 94.32,41.92 58.92,41.92 57.91,42.93 57.91,46.41 58.67,47.17 58.67,48.84 58.17,49.35 51.68,49.35 51.44,49.1 50.67,49.1 47.88,51.89 47.88,53.34 46.74,54.48 43.18,54.48 42.54,53.85 40.26,53.85 39.75,53.34 39.75,51.31 37.7,49.26 33.04,49.26 30.99,51.31 v1(30.99,52.2)
ADAU1452_MP11: length 23.9
  TOP w0.178: U6.61 v1(25.88,42.28)
  L3_SIG w0.178: v1(34.04,45.09) 26.8,45.09 25.88,44.17 v1(25.88,42.28)
  BOTTOM w0.178: v1(34.04,45.09) 34.04,46.48 35.94,48.39 42.16,48.39 43.81,50.04
ADAU1452_SCL: length 138.2
  TOP w0.178: R79.2 v1(38.44,40.51)
  TOP w0.203: R25.2 143.64,8.13 143.88,8.37 143.88,10.86 140.93,13.82 137.39,13.82 137.03,13.46 132.59,13.46 v1(131.83,14.22) R53.1 131.06,15.61 U27.2 ; v1(47.24,39.62) 47.66,40.04 47.66,45.38 48.52,46.24 R132.2
  L3_SIG w0.178: v1(131.83,14.22) 131.2,13.59 129.18,13.59 128.76,14.01 128.76,14.37 125.62,17.51 119.67,17.51 118.62,18.57 118.62,23.05 116.91,24.77 113.54,24.77 113.16,25.15 113.16,25.4 111.42,27.14 103.52,27.14 101.66,29 101.66,30.78 99.63,32.8 99.63,33.91 99.13,34.42 98.11,34.42 92.89,39.64 47.26,39.64 v1(47.24,39.62) 42.51,39.62 41.12,41.02 39.62,41.02 39.5,40.89 38.82,40.89 v1(38.44,40.51)
ADAU1452_SDA: length 140.6
  TOP w0.178: R77.2 v1(38.44,41.66)
  TOP w0.203: v1(68.77,40.26) 68.77,44.01 67.69,45.09 R138.2 ; U26.2 135.89,14.23 R39.1 v1(136.66,14.22) 141.1,14.22 144.29,11.03 144.29,7.06 144.09,6.86 R29.2
  L3_SIG w0.178: v1(38.44,41.66) 38.82,41.27 39.34,41.27 39.47,41.4 41.28,41.4 42.42,40.26 v1(68.77,40.26) 92.81,40.26 98.27,34.8 99.29,34.8 102.04,32.05 102.04,29.15 103.67,27.52 111.58,27.52 113.06,26.03 116.17,26.03 119,23.21 119,18.72 119.83,17.89 125.77,17.89 128.68,14.99 135.89,14.99 v1(136.66,14.22)
ADAU1452_SELFBOOT: length 142.3
  TOP w0.178: R93.2 JP2.2 151.13,14.1 v1(149.35,14.1) 148.59,14.86 U25.2
  TOP w0.203: U6.34 35.66,44.28 36,44.62 39.66,44.62 v1(40.51,45.47)
  L3_SIG w0.178: v1(149.35,14.1) 148.83,13.58 148.1,13.58 147.07,14.61 147.07,21.4 145.73,22.73 127.67,22.73 126.4,24 119.82,24 116.65,27.18 113.54,27.18 112.05,28.66 104.15,28.66 103.18,29.63 103.18,32.52 94.16,41.54 51.04,41.54 48.51,44.07 47.62,44.07 47.24,43.69 43.18,43.69 41.4,45.47 v1(40.51,45.47)
ADAU1452_SPDIFIN: length 70.6
  TOP w0.178: R193.1 25.02,30.86 25.4,30.48 25.91,30.48 26.52,29.87 26.52,28.22 27.18,27.56 31.12,27.56 v1(31.88,26.8) ; R127.2 R226.2 v1(85.72,23.49)
  L3_SIG w0.178: v1(31.88,26.8) 35.56,23.11 51.82,23.11 52.32,22.61 54.86,22.61 55.12,22.35 70.99,22.35 72.14,23.49 v1(85.72,23.49)
ADAU1452_SPDIFIN_OPT: length 4.7
  TOP w0.178: R127.1 C177.2
  TOP w0.203: R119.2 R103.2 C177.2
ADAU1452_SPDIFIN_RCA: length 56
  TOP w0.178: v1(84.07,26.92) 84.07,19.81 84.45,19.44 R226.1
  L3_SIG w0.178: v1(84.07,26.92) 67.94,26.92 66.55,25.53 61.09,25.53 60.59,25.03 53.61,25.03 v1(53.09,24.51)
  BOTTOM w0.178: v1(53.09,24.51) 53.96,23.63 53.96,18.09 58.15,13.9 U20.2
ADAU1452_SPDIFOUT: length 81.6
  TOP w0.178: R116.2 26.16,30.86 26.92,30.1 26.92,28.7 27.56,28.07 31.5,28.07 v1(31.88,27.69) ; R227.2 R228.2 v1(95.5,23.88)
  L3_SIG w0.178: v1(95.5,23.88) 89.15,23.88 88.9,24.13 72.01,24.13 70.74,22.86 55.37,22.86 54.36,23.88 52.45,23.88 52.2,23.62 35.94,23.62 v1(31.88,27.69)
ADAU1452_SPDIFOUT_OPT: length 6
  TOP w0.203: P6.3 C178.2 96.64,15.25 96.64,17.4 R227.1
ADAU1452_SPDIFOUT_RCA: length 60.4
  TOP w0.178: R228.1 94.1,17.41 93.6,17.91 v1(93.6,24.64)
  L3_SIG w0.203: v1(93.6,24.64) 71.96,24.64 70.69,23.37 61.72,23.37 60.58,24.51 v1(54.36,24.51)
  BOTTOM w0.203: U20.5 57.22,17.71 54.36,20.57 v1(54.36,24.51)
ADC1LN: length 26.9
  TOP w0.241: U7.54 54.03,33.95 54.03,33.04 54.02,33.04 54.02,32.5 v1(54.27,32.26)
  BOTTOM w0.241: C134.2 39.62,26.37 39.32,26.67 39.32,27.91 42.44,31.03 50.27,31.03 51.14,30.16 53.09,30.16 54.04,31.12 54.04,32.03 v1(54.27,32.26) ; C134.2 C133.2 ; C134.2 39.62,25.71 39.35,25.44 39.35,23.8 39.59,23.56 C142.2
ADC1LP: length 26.9
  TOP w0.241: U7.53 53.62,33.96 53.62,33.21 53.62,33.21 53.62,32.47 53.57,32.42 v1(53.4,32.26)
  BOTTOM w0.241: C134.1 38.62,26.28 38.78,26.44 38.78,26.54 38.91,26.67 38.91,28.08 42.27,31.44 50.44,31.44 51.31,30.57 52.92,30.57 53.63,31.28 53.63,32.03 v1(53.4,32.26) ; C134.1 C135.2 ; C134.1 38.62,25.71 38.94,25.38 38.94,23.8 38.7,23.56 C143.2
ADC1RN: length 45.8
  TOP w0.241: U7.56 55.03,34.04 55.03,36.56 55.08,36.61 55.08,36.65 v1(55.37,36.94)
  BOTTOM w0.241: v1(55.37,36.94) 55.03,37.28 55.03,38.7 53.78,39.94 51.11,39.94 43.94,32.77 40.01,32.77 39.24,32 36.39,32 33.24,28.85 27.71,28.85 26.72,27.86 26.72,26.8 26.42,26.5 C139.2 ; C140.2 C139.2 ; C139.2 26.42,25.65 26.72,25.35 26.72,23.8 26.48,23.56 C147.2
ADC1RP: length 44.5
  TOP w0.241: U7.55 54.62,34.05 54.62,36.6 v1(54.28,36.94)
  BOTTOM w0.241: C144.2 27.37,23.56 27.13,23.8 27.13,25.35 27.42,25.65 C139.1 ; C136.2 C139.1 ; C139.1 27.42,26.5 27.13,26.8 27.13,27.7 27.88,28.45 33.4,28.45 36.55,31.6 39.41,31.6 40.17,32.36 44.11,32.36 51.28,39.54 53.62,39.54 54.62,38.53 54.62,37.28 v1(54.28,36.94)
ADP2360_EN: length 3.5
  BOTTOM w0.203: U19.1 84.9,62.17 85.41,62.67 85.67,62.67 R159.2 86.17,63.17 86.17,63.49 R154.2
ADP2360_PG: length 73.5
  TOP w0.178: v1(117.35,28.32) JP1.1 R125.2
  L3_SIG w0.178: v1(85.03,61.52) 85.03,60.26 79.62,54.85 79.62,48.81 85.74,42.68 94.63,42.68 99.33,37.99 100.31,37.99 104.15,34.15 105.18,34.15 109.53,29.8 112.53,29.8 114.01,28.32 v1(117.35,28.32)
  BOTTOM w0.178: R161.1 85.59,61.52 v1(85.03,61.52) U19.2
ADR1/SPISS0: length 201.5
  TOP w0.178: R89.1 14.05,37.21 14.22,37.39 14.22,41.53 13.72,42.04 v1(11.61,42.04)
  L3_SIG w0.178: JP42.1 163.99,7.75 158.62,7.75 156.21,10.16 152.12,10.16 151.14,9.19 135.78,9.19 132.73,6.14 115.03,6.14 106.45,14.72 86.66,14.72 86.26,15.11 83.69,15.11 82.8,14.22 79.76,14.22 79.5,14.48 58.67,14.48 57.53,15.62 47.66,15.62 45.83,17.44 21.73,17.44 18.68,14.4 13.7,14.4 13.13,14.97 13.13,17.89 9.27,21.75 9.27,28.19 10.92,29.84 10.92,41.35 v1(11.61,42.04)
  BOTTOM w0.203: R177.1 v1(11.61,42.04)
ADR2/IO2/MCLK: length 167.9
  TOP w0.178: R49.2 v1(29.21,50.93) R140.2 ; v1(40.26,50.16) 41.15,50.16 41.92,49.39 41.92,41.29 JP38.3 ; R242.1 v1(113.79,25.4) R12.1 R21.2 ; v1(64.47,35.31) R91.2
  L3_SIG w0.178: P15.31 28.45,53.98 29.21,53.21 v1(29.21,50.93) 29.21,50.93 31.65,48.5 39.35,48.5 40.26,49.4 v1(40.26,50.16)
  BOTTOM w0.178: P15.31 17.14,52.78 17.14,48.01 17.53,47.62 19.05,47.62 19.46,47.22 19.46,42.9 19.94,42.42 19.94,35.69 19.18,34.92 15.1,34.92 14.68,35.34 14.68,36.88 14.1,37.46 10.94,37.46 10.03,36.56 10.03,34.15 9.86,33.97 P32.47 ; JP38.3 41.15,38.99 48.51,38.99 50.42,40.89 58.86,40.89 64.45,35.31 v1(64.47,35.31) 65.25,36.08 96.64,36.08 96.89,35.83 96.89,31.03 103.12,24.79 103.12,24.38 103.63,23.88 112.27,23.88 v1(113.79,25.4)
BCLK_IN0: length 2.2
  TOP w0.178: U6.57 24.29,44.28 R62.1
DAC1LN: length 34.2
  TOP w0.241: v1(59.51,32.77) 59.86,33.12 59.86,34.63 58.33,36.16 58.33,38.82 55.68,41.47 51.04,41.47 50.99,41.43 U7.37
  BOTTOM w0.241: v1(59.51,32.77) 59.84,32.43 59.84,32.03 58.86,31.06 58.86,28.14 59.89,27.11 65.63,27.11 65.88,26.86 65.88,24.79 65.48,24.4 64.69,24.4 64.44,24.64 R194.1
DAC1LP: length 35.5
  TOP w0.241: U7.36 50.99,41.93 51.04,41.88 55.85,41.88 58.74,38.99 58.74,36.33 60.26,34.8 60.26,33.09 v1(60.59,32.77)
  BOTTOM w0.241: v1(60.59,32.77) 60.25,32.43 60.25,31.87 59.27,30.89 59.27,28.31 60.06,27.52 65.79,27.52 66.28,27.03 66.28,24.63 65.65,23.99 64.69,23.99 64.44,23.75 R192.1
DAC1RN: length 40.6
  TOP w0.241: U7.39 50.99,40.43 51.04,40.47 55.22,40.47 56.3,39.39 56.3,38.82 v1(55.96,38.48)
  BOTTOM w0.241: R212.1 44.97,24.13 44.72,23.89 44.38,23.89 43.94,24.33 43.94,26.23 47.37,29.65 48.83,29.65 49.53,28.96 53.78,28.96 58.86,34.04 58.86,39.3 58.39,39.78 56.78,39.78 56.3,39.3 56.3,38.82 v1(55.96,38.48)
DAC1RP: length 40.6
  TOP w0.241: v1(57.04,38.48) 56.71,38.82 56.71,39.56 55.39,40.88 51.04,40.88 50.99,40.93 U7.38
  BOTTOM w0.241: R211.1 44.97,23.24 44.72,23.48 44.21,23.48 43.54,24.16 43.54,26.39 47.2,30.06 49,30.06 49.7,29.36 53.62,29.36 58.46,34.2 58.46,39.13 58.22,39.37 56.95,39.37 56.71,39.13 56.71,38.82 v1(57.04,38.48)
HW_RESET: length 142.8
  TOP w0.203: v1(114.87,67.12) R1.1
  L3_SIG w0.203: v1(6.79,36.51) 5.59,37.71 5.59,47.62 8.38,50.42 8.38,56.39 11.81,59.82 25.97,59.82 27.11,60.96 35.71,60.96 36.75,62 39.9,62 43.61,65.71 48.59,65.71 51.82,62.48 56.76,62.48 58.31,64.03 62.07,64.03 63.81,62.29 79.44,62.29 82.68,65.53 89.92,65.53 90.42,65.02 90.42,62.97 90.63,62.76 98.57,62.76 102.04,66.23 110.69,66.23 111.58,67.12 v1(114.87,67.12)
  BOTTOM w0.178: P32.55 v1(6.79,36.51)
I2C_BUS_SWITCH: length 27.7
  TOP w0.203: R238.1 149.54,19.36 U25.4 149.54,17.09 149.34,16.89 147.19,16.89 146.94,16.64 146.94,16 145.54,14.61 141.86,14.61 141.6,14.86 U28.2 141.6,16.38 141.22,16.76 140.21,16.76 139.83,16.38 139.83,15.75 139.57,15.49 138.43,15.49 137.41,16.51 135.51,16.51 135.24,16.24 U26.1 133.13,15.62 132.36,16.39 130.56,16.39 130.41,16.24 U27.1
L_CH_THRU: length 15.4
  BOTTOM w0.508: P28.4 43.78,9.5 42.29,10.99 32.94,10.99 31.81,9.86 P29.4
LRCLK_IN0: length 1.9
  TOP w0.178: U6.58 23.65,43.78 R63.1
LT3502_VFB: length 2.6
  BOTTOM w0.203: U16.3 59.38,62.39 58.98,62.79 R160.2 R184.2
LTC4368_SENSE: length 5.2
  TOP w0.254: U3.9 54.22,58.48 56.31,60.57 R18.1
  vias: v1(47.62,68.07) v1(47.62,67.44) v1(48.26,68.07) v1(48.26,67.44) v1(56.9,64.83) v1(56.9,64.14) v1(57.66,64.83) v1(57.66,64.14)
LTC4368_SHDN*: length 123
  TOP w0.254: R27.2 v1(53.66,55.97)
  BOTTOM w0.178: v1(53.66,55.97) 53.66,55.94 53.21,55.5 51.56,55.5 50.67,54.61 50.67,51.82 51.94,50.55 51.94,48.89 53.09,47.75 56.64,47.75 63.88,40.51 67.03,40.51 68.71,38.83 95.73,38.83 97.65,36.91 97.65,32.42 105.3,24.77 111.23,24.77 111.75,25.28 111.75,25.61 112.44,26.3 115.66,26.3 116.81,25.15 120.01,25.15 120.87,24.29 124.36,24.29 125.79,22.86 136.4,22.86 137.29,23.75 JP4.2
LTC4368_WAKEUP: length 12.9
  TOP w0.381: 146.4,36.07 144.41,36.07 R42.2 143.25,36.08 141.99,37.34 136.53,37.34 JP4.3
PDM_CLK: length 5.9
  TOP w0.203: R157.2 108.97,18.29 109.47,18.8 111,18.8 JP1.3
PDM_DATA0: length 69.6
  TOP w0.203: R131.2 v1(102.37,15.75) ; R130.2 124.8,18.29 C84.2 v1(124.93,19.11)
  BOTTOM w0.203: JP6.3 93.56,29.88 93.95,29.49 93.95,26.88 94.36,26.48 94.36,21.36 99.14,16.59 101.53,16.59 v1(102.37,15.75) 108.69,9.43 108.69,2.74 109.31,2.12 115.78,2.12 117.47,3.81 117.47,12.57 121.79,16.89 122.71,16.89 v1(124.93,19.11)
PDM_DATA1: length 58.2
  TOP w0.203: R158.2 C100.2 v1(116.93,4.03) ; R141.2 v1(114.37,12.76)
  BOTTOM w0.203: JP9.3 94.53,29.88 94.36,29.72 94.36,27.05 94.84,26.57 94.84,21.59 99.44,16.99 102.01,16.99 109.09,9.91 109.09,2.91 109.48,2.52 115.42,2.52 v1(116.93,4.03) 116.93,11.72 115.89,12.76 v1(114.37,12.76)
R_CH_THRU: length 17.7
  BOTTOM w0.508: P28.5 40.8,7.87 40.3,7.37 27.32,7.37 26.81,7.87 P29.5
SDATA_OUT0: length 4.5
  TOP w0.178: U6.41 32.21,47.18 33.16,48.13 33.76,48.13 34.19,48.56 34.19,48.8 R47.1
SDATA_OUT1: length 3.7
  TOP w0.178: R48.1 32,48.77 30.71,47.47 U6.44
SLAVE_ADDR0: length 4.6
  TOP w0.178: U6.33 34.85,43.84 34.45,43.84 34.35,43.94 v1(34.04,43.94)
  BOTTOM w0.178: R178.2 33.9,40.94 34.67,41.71 34.67,43.31 v1(34.04,43.94)
SLAVE_ADDR1: length 2.1
  TOP w0.178: U6.32 34.85,43.23 34.45,43.23 34.41,43.18 v1(34.04,43.18)
  BOTTOM w0.178: R179.2 34.04,42.17 v1(34.04,43.18)
UNNAMED_3_AD243XW_I149_ACM: length 0.8
  TOP w0.203: U9.27 v1(112.63,33.42)
UNNAMED_3_AD243XW_I149_ADR1: length 9.7
  TOP w0.178: U9.22 111.69,29.02 112.27,28.45 R195.2 112.37,27.42 112.93,26.86 112.93,24.66 R22.1 R135.2
UNNAMED_3_AD243XW_I149_ADR2: length 5
  TOP w0.178: R242.2 113.79,27.81 112.19,29.41 U9.23
UNNAMED_3_AD243XW_I149_BCLK: length 5.5
  TOP w0.178: R241.2 102.23,32.38 104.01,34.16 105.28,34.16 105.52,33.93 U9.9
UNNAMED_3_AD243XW_I149_GPIO7: length 4.9
  TOP w0.178: U9.14 107.69,29.84 106.3,28.45 R14.2
UNNAMED_3_AD243XW_I149_ISENSEN: length 8.1
  TOP w0.203: U9.36 112.9,37.92 112.69,38.13 U9.37 112.69,40.68 114.05,42.04 115.59,42.04 116.46,42.9 R72.2
UNNAMED_3_AD243XW_I149_MISO: length 4.4
  TOP w0.178: U9.17 109.19,28.8 108.84,28.45 R120.2
UNNAMED_3_AD243XW_I149_MOSI: length 4.4
  TOP w0.178: U9.18 109.69,28.74 109.98,28.45 R11.2
UNNAMED_3_AD243XW_I149_SCK: length 4.7
  TOP w0.178: R199.2 111.12,28.32 110.19,29.25 U9.19
UNNAMED_3_AD243XW_I149_SIO0: length 19.8
  TOP w0.178: JP6.2 93.56,33.66 96.72,33.66 96.9,33.83 96.9,37.08 98.04,38.23 ; 98.81,38.23 101.67,38.23 101.85,38.05 C41.1 102.62,37.46 104.16,35.92 U9.5
  TOP w0.203: 98.81,38.23 98.04,38.23
UNNAMED_3_AD243XW_I149_SIO1: length 5
  TOP w0.178: R54.2 102.49,36.2 103.26,35.42 U9.6
UNNAMED_3_AD243XW_I149_SIO2: length 4.6
  TOP w0.178: R98.2 U9.7
UNNAMED_3_AD243XW_I149_SIO3: length 5.2
  TOP w0.178: U9.12 103.67,32.42 102.36,31.12 R114.2
UNNAMED_3_AD243XW_I149_SIO4: length 5.1
  TOP w0.178: U9.13 107.19,29.98 105.16,27.94 R121.2
UNNAMED_3_AD243XW_I149_SWN: length 6.5
  TOP w0.203: R73.2 114.25,42.94 112.17,40.86 112.17,39.65 111.69,39.18 U9.39
UNNAMED_3_AD243XW_I149_SYNC: length 5.1
  TOP w0.178: U9.8 105.56,34.42 105.44,34.54 103.25,34.54 102.36,33.66 R240.2
UNNAMED_3_CAP_I12_N1: length 8.5
  TOP w0.178: R54.1 C51.1 99.81,35.55 99.69,35.43 97.66,35.43 97.28,35.05 97.28,32.64 97.07,32.42 JP9.2
UNNAMED_3_DIOLED_I84_P: length 1.4
  TOP w0.178: DS10.A R34.1
UNNAMED_3_DIOLED_I208_P: length 1.4
  TOP w0.178: DS9.A R38.1
UNNAMED_3_IC24XX512_I97_A0: length 3.3
  TOP w0.203: U15.1 v1(118.49,10.67) R148.1
  BOTTOM w0.203: R147.2 v1(118.49,10.67)
UNNAMED_3_IC24XX512_I97_A1: length 3.3
  TOP w0.203: U15.2 v1(118.49,9.4) R139.1
  BOTTOM w0.203: R146.2 v1(118.49,9.4)
UNNAMED_3_IC24XX512_I97_A2: length 3.3
  TOP w0.203: R137.1 v1(118.49,8.13) 120.14,8.13
  BOTTOM w0.203: R133.2 v1(118.49,8.13)
UNNAMED_3_IC24XX512_I97_SCL: length 2
  TOP w0.203: 125.22,8.13 R35.1
UNNAMED_3_IC24XX512_I97_SDA: length 2
  TOP w0.203: U15.5 R203.1
UNNAMED_3_IC24XX512_I97_WP: length 3.3
  TOP w0.203: U15.7 R244.2 R243.1
UNNAMED_4_CAP_I21_N1: length 6.3
  TOP w0.241: C70.1 147.51,27 146.19,27 R41.2 144.68,26.92 143.39,26.92 143.09,27.22 FL2.4
UNNAMED_4_CAP_I21_N2: length 9.8
  TOP w0.241: T1.2 158.43,27.11 158.3,26.99 150.03,26.99 C70.2
UNNAMED_4_CAP_I24_N2: length 17.3
  TOP w0.305: C65.2 147.79,22.94 R40.1 v1(145.47,21.7) ; C80.1 147.81,30.51 R41.1 v1(145.47,31.75)
  BOTTOM w0.305: v1(145.47,21.7) 145.47,21.7 v1(145.47,31.75)
UNNAMED_4_CAP_I25_N1: length 6.4
  TOP w0.241: C68.1 147.51,26.59 146.32,26.59 R40.2 144.69,26.51 143.35,26.51 143.05,26.21 FL2.3
UNNAMED_4_CAP_I25_N2: length 9.8
  TOP w0.241: C68.2 150.01,26.58 158.33,26.58 158.45,26.46 T1.1
UNNAMED_4_CAP_I67_N2: length 7.4
  TOP w0.508: L2.1 130.97,24.23 v1(132.14,24.23) ; L3.2 130.98,29.18 v1(132.14,29.18)
  BOTTOM w0.584: v1(132.14,29.18) 132.14,26.73 C33.2 132.14,26.68 v1(132.14,24.23)
UNNAMED_4_CAP_I73_N1: length 6.5
  TOP w0.241: L5.2 133.82,26.96 134.51,26.96 C35.1 134.98,26.93 139.07,26.93 139.36,27.22 FL2.1
UNNAMED_4_CAP_I74_N2: length 6.6
  TOP w0.241: FL2.2 139.4,26.21 139.08,26.52 134.98,26.52 C34.2 134.5,26.51 133.86,26.51 L4.2
UNNAMED_4_CAP_I91_N1: length 1.3
  TOP w0.178: T1.5 162.95,25.27 C72.1
UNNAMED_4_CAP_I138_N2: length 2.4
  TOP w0.508: R65.2 160.78,35.93 C44.2 C98.2
UNNAMED_4_CAP_I139_N1: length 31.4
  TOP w0.241: TP26.1 156.6,34.93 C98.1 158.76,34.54 158.76,29.73 158.58,29.55 T1.3
  BOTTOM w0.508: R46.2 165.11,18.42 166.12,19.43 166.12,27.87 159.06,34.92 TP26.1
UNNAMED_4_MODRJE7318800XXX_I171_2: length 8.1
  L4_PWR w0.508: 169.07,29.52 P22.11 169.07,27.79 ; 170.67,23.45 P22.3 170.67,21.86 ; 170.67,27.53 P22.7 ; 174.05,20.84 P22.2 174.05,22.43
UNNAMED_4_MODRJE7318800XXX_I171_4: length 12.4
  TOP w0.241: P22.4 170.61,23.68 170,24.29 168.79,24.29 164.45,28.63 163.63,28.63 163.51,28.51 T1.6
UNNAMED_4_MODRJE7318800XXX_I171_5: length 10.4
  TOP w0.241: T1.7 163.5,29.16 163.62,29.04 164.62,29.04 168.96,24.7 P22.5
UNNAMED_4_MODRJE7318800XXX_I171_LED1C: length 2.5
  BOTTOM w0.508: P22.12 168.2,33.45 R247.1
UNNAMED_4_TRANOPTO4PV2_I78_C: length 17.9
  TOP w0.241: T1.4 159.35,29.63 159.17,29.81 159.17,34.46 C44.1 v1(161.16,34.93)
  TOP w0.508: 152.56,36.07 v1(154,36.07)
  BOTTOM w0.508: v1(161.16,34.93) 161.16,34.93 158.5,37.59 155.52,37.59 v1(154,36.07)
UNNAMED_5_CAP_I12_N1: length 17.3
  TOP w0.305: C24.2 155.44,47.99 R56.1 v1(153.09,49.23) ; v1(153.09,39.14) R78.1 C39.1
  BOTTOM w0.305: v1(153.09,49.23) v1(153.09,39.14)
UNNAMED_5_CAP_I100_N2: length 14.2
  TOP w0.241: FL1.2 147,43.63 146.69,43.93 134.98,43.93 C49.2 134.53,43.89 133.83,43.89 L10.2
UNNAMED_5_CAP_I102_N2: length 7.2
  TOP w0.508: v1(132.08,41.7) L8.1 ; v1(132.08,46.58) L9.2
  BOTTOM w0.508: v1(132.08,41.7) 132.08,44.1 C48.2 132.08,44.17 v1(132.08,46.58)
UNNAMED_5_CAP_I105_N1: length 14.2
  TOP w0.241: L11.2 133.86,44.35 133.86,44.33 134.48,44.33 C50.1 134.98,44.34 146.7,44.34 147,44.64 FL1.1
UNNAMED_5_CAP_I116_N1: length 17.3
  L4_PWR w0.508: 170.67,44.34 P10.3 170.67,45.93 ; 174.05,43.32 P10.2 174.05,44.91 ; 170.67,50.01 P10.7 ; P10.11 169.07,50.27 ; P10.11 167.33,52 ; P10.11 169.07,52 ; P10.11 167.33,50.27
  BOTTOM w0.508: 109.22,52.42 C116.1 ; C116.1 109.8,52.97 ; C116.1 108.64,52.97 ; 106.46,52.95 D6.C ; D6.C 108.17,52.95 ; D6.C 107.31,52.1 ; 167.33,50.27 P10.11 169.07,50.27
  vias: v1(164.53,51.37) v1(164.53,50.74) v1(164.53,50.1) v1(165.16,51.37) v1(165.16,50.74) v1(165.16,50.1) v1(165.8,51.37) v1(165.8,50.74) v1(165.8,50.1)
UNNAMED_5_CAP_I116_N2: length 1.7
  BOTTOM w0.635: C117.2 R168.1
UNNAMED_5_CAP_I145_N2: length 18.4
  TOP w0.241: P10.4 170.6,46.15 169.98,46.77 166.72,46.77 163.88,43.93 159.63,43.93 158.89,43.19 L6.2 158.61,43.19 157.89,43.92 157.54,43.92 C53.2
UNNAMED_5_CAP_I146_N1: length 6.4
  TOP w0.241: FL1.4 150.69,44.64 150.99,44.34 152.23,44.34 R56.2 153.95,44.33 155.22,44.33 C54.1
UNNAMED_5_CAP_I146_N2: length 16.4
  TOP w0.241: P10.5 166.55,47.17 163.72,44.34 159.63,44.34 158.89,45.07 L1.1 158.61,45.07 157.86,44.32 157.56,44.32 C54.2
UNNAMED_5_DIOSCHOTTKY_I144_P: length 2.2
  BOTTOM w0.635: R220.1 109.48,55.76 D6.A
UNNAMED_5_FLTR4PV7_I16_N3: length 6.3
  TOP w0.241: FL1.3 150.69,43.63 150.99,43.93 152.34,43.93 R78.2 153.83,43.92 155.22,43.92 C53.1
UNNAMED_5_MODRJE7318800XXX_I184_LED1C: length 2.5
  BOTTOM w0.508: R249.1 168.2,56.06 P10.12
UNNAMED_5_MODRJE7318800XXX_I184_LED2C: length 2.1
  BOTTOM w0.508: R248.2 P10.10
UNNAMED_5_RES_I124_N1: length 2.3
  BOTTOM w0.635: R165.1 110.5,55.74 R220.2 110.5,55.77 R166.1
UNNAMED_7_741G125_I116_B: length 3
  BOTTOM w0.203: U4.4 10.65,33.64 9.72,32.7 P32.43
UNNAMED_7_7408V3_I90_A: length 2.5
  TOP w0.203: R1.2 R2.2 U1.1
UNNAMED_7_7408V3_I100_A: length 8.2
  TOP w0.203: U24.1 120.51,65.96 120.1,65.55 118.18,65.55 117.6,64.98 117.6,63.75 117.16,63.32 116.27,63.32 115.65,62.69 U1.4
UNNAMED_7_7408V3_I100_B: length 10.3
  TOP w0.203: R136.2 112.98,68.3 116.68,68.3 117.21,67.76 R101.2 117.21,66.61 C131.2 117.77,66.05 119.04,66.05 119.56,66.57 U24.2
UNNAMED_7_7408V3_I100_Y: length 3.6
  TOP w0.203: R9.2 U2.3 118.61,62.72 U24.4
UNNAMED_7_ADM6315_I36_RESETN: length 1.5
  TOP w0.203: U2.2 R8.2
UNNAMED_7_CN32PODDEVEN_I115_N3: length 13.2
  TOP w0.203: P15.5 17.08,22.22 17.08,26.99 16.76,27.3 14.73,27.3 14.31,27.72 14.31,29.03 v1(13.37,29.97)
  BOTTOM w0.203: v1(13.37,29.97) 13.37,30.65 13.45,30.73 R189.2
UNNAMED_7_CN100PV2_I48_N20: length 127.1
  TOP w0.203: R125.1 v1(117.35,16.12)
  L3_SIG w0.203: v1(11.56,29.97) 11.56,24.89 14.35,22.1 19.18,22.1 19.56,21.72 19.56,19.94 20.7,18.8 30.39,18.8 31.03,19.43 34.68,19.43 36.13,17.98 46.66,17.98 47.65,16.99 67.27,16.99 67.4,16.87 69.82,16.87 70.23,17.27 70.87,17.27 72.22,18.63 96.16,18.63 98.44,16.34 105.38,16.34 109.9,11.82 115.46,11.82 117.35,13.72 v1(117.35,16.12)
  BOTTOM w0.178: v1(11.56,29.97) 11.56,30.61 10.73,31.43 P32.39
UNNAMED_7_CN100PV2_I48_N38: length 1.9
  BOTTOM w0.203: P32.75 R177.2
UNNAMED_7_CN100PV2_I56_N43: length 9.9
  BOTTOM w0.254: R169.1 8.01,52.33 6.67,50.99 6.67,46.42 6.29,46.04 P32.86
UNNAMED_7_CN100PV2_I56_N44: length 2.1
  BOTTOM w0.254: P32.88 R174.1
UNNAMED_7_DIOLED_I69_N: length 1.6
  TOP w0.203: R4.2 DS1.C
UNNAMED_7_RES_I25_N2: length 4.4
  TOP w0.203: R3.2 R6.2 R134.2 R4.1 R8.1
UNNAMED_7_RES_I97_N1: length 8.9
  TOP w0.381: R136.1 107.7,67.19 107.31,66.81 107.31,65.71 SW1.3 SW1.2
UNNAMED_8_ADAU145X_I261_AVDD: length 3.1
  TOP w0.254: C61.2 33.01,35.11 32.71,35.42 U6.15 ; U6.7 28.71,34.91 C62.2
UNNAMED_8_ADAU145X_I261_BCLKIN3: length 2.2
  TOP w0.178: U6.68 24.17,38.78 R87.2
UNNAMED_8_ADAU145X_I261_BCLKOUT0: length 4.9
  TOP w0.178: U6.40 32.71,47.06 33.4,47.75 33.92,47.75 34.68,48.51 35.04,48.51 R45.1
UNNAMED_8_ADAU145X_I261_BCLKOUT1: length 4.1
  TOP w0.178: U6.43 31.21,47.43 32.32,48.55 32.49,48.55 33.1,49.16 R176.1
UNNAMED_8_ADAU145X_I261_BCLKOUT2: length 3.4
  TOP w0.178: U6.48 28.71,48.14 29.21,48.64 R140.1
UNNAMED_8_ADAU145X_I261_BCLKOUT3: length 3.8
  TOP w0.178: U6.51 27.21,47.73 R51.1
